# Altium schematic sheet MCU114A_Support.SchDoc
size 431 x 279 mm; Date: Not shown in title block; ApprovedBy: Not shown in title block; CheckedBy: Not shown in title block; Author: Not shown in title block; CompanyName: Not shown in title block; Engineer: Not shown in title block; Organization: Not shown in title block; Address1: Not shown in title block; Address2: Not shown in title block; Address3: Not shown in title block; Address4: Not shown in title block; DocumentNumber: 3; Revision: Use project parameter SCH_Rev; SheetNumber: 3; SheetTotal: 11; PageSetup: Record=PageOptions¦CenterHorizontal=True¦CenterVertical=True¦PrintScale=1.00¦XCorrection=1.00¦YCorrection=1.00¦PrintKind=0¦BorderSize=5000000¦LeftOffset=0¦BottomOffset=0¦Orientation=2¦PaperLength=1000¦PaperWidth=1000¦Scale=100¦PaperSource=15¦PrintQuality=600¦MediaType=1¦DitherType=10¦PaperKind=Letter¦PrintScaleMode=1
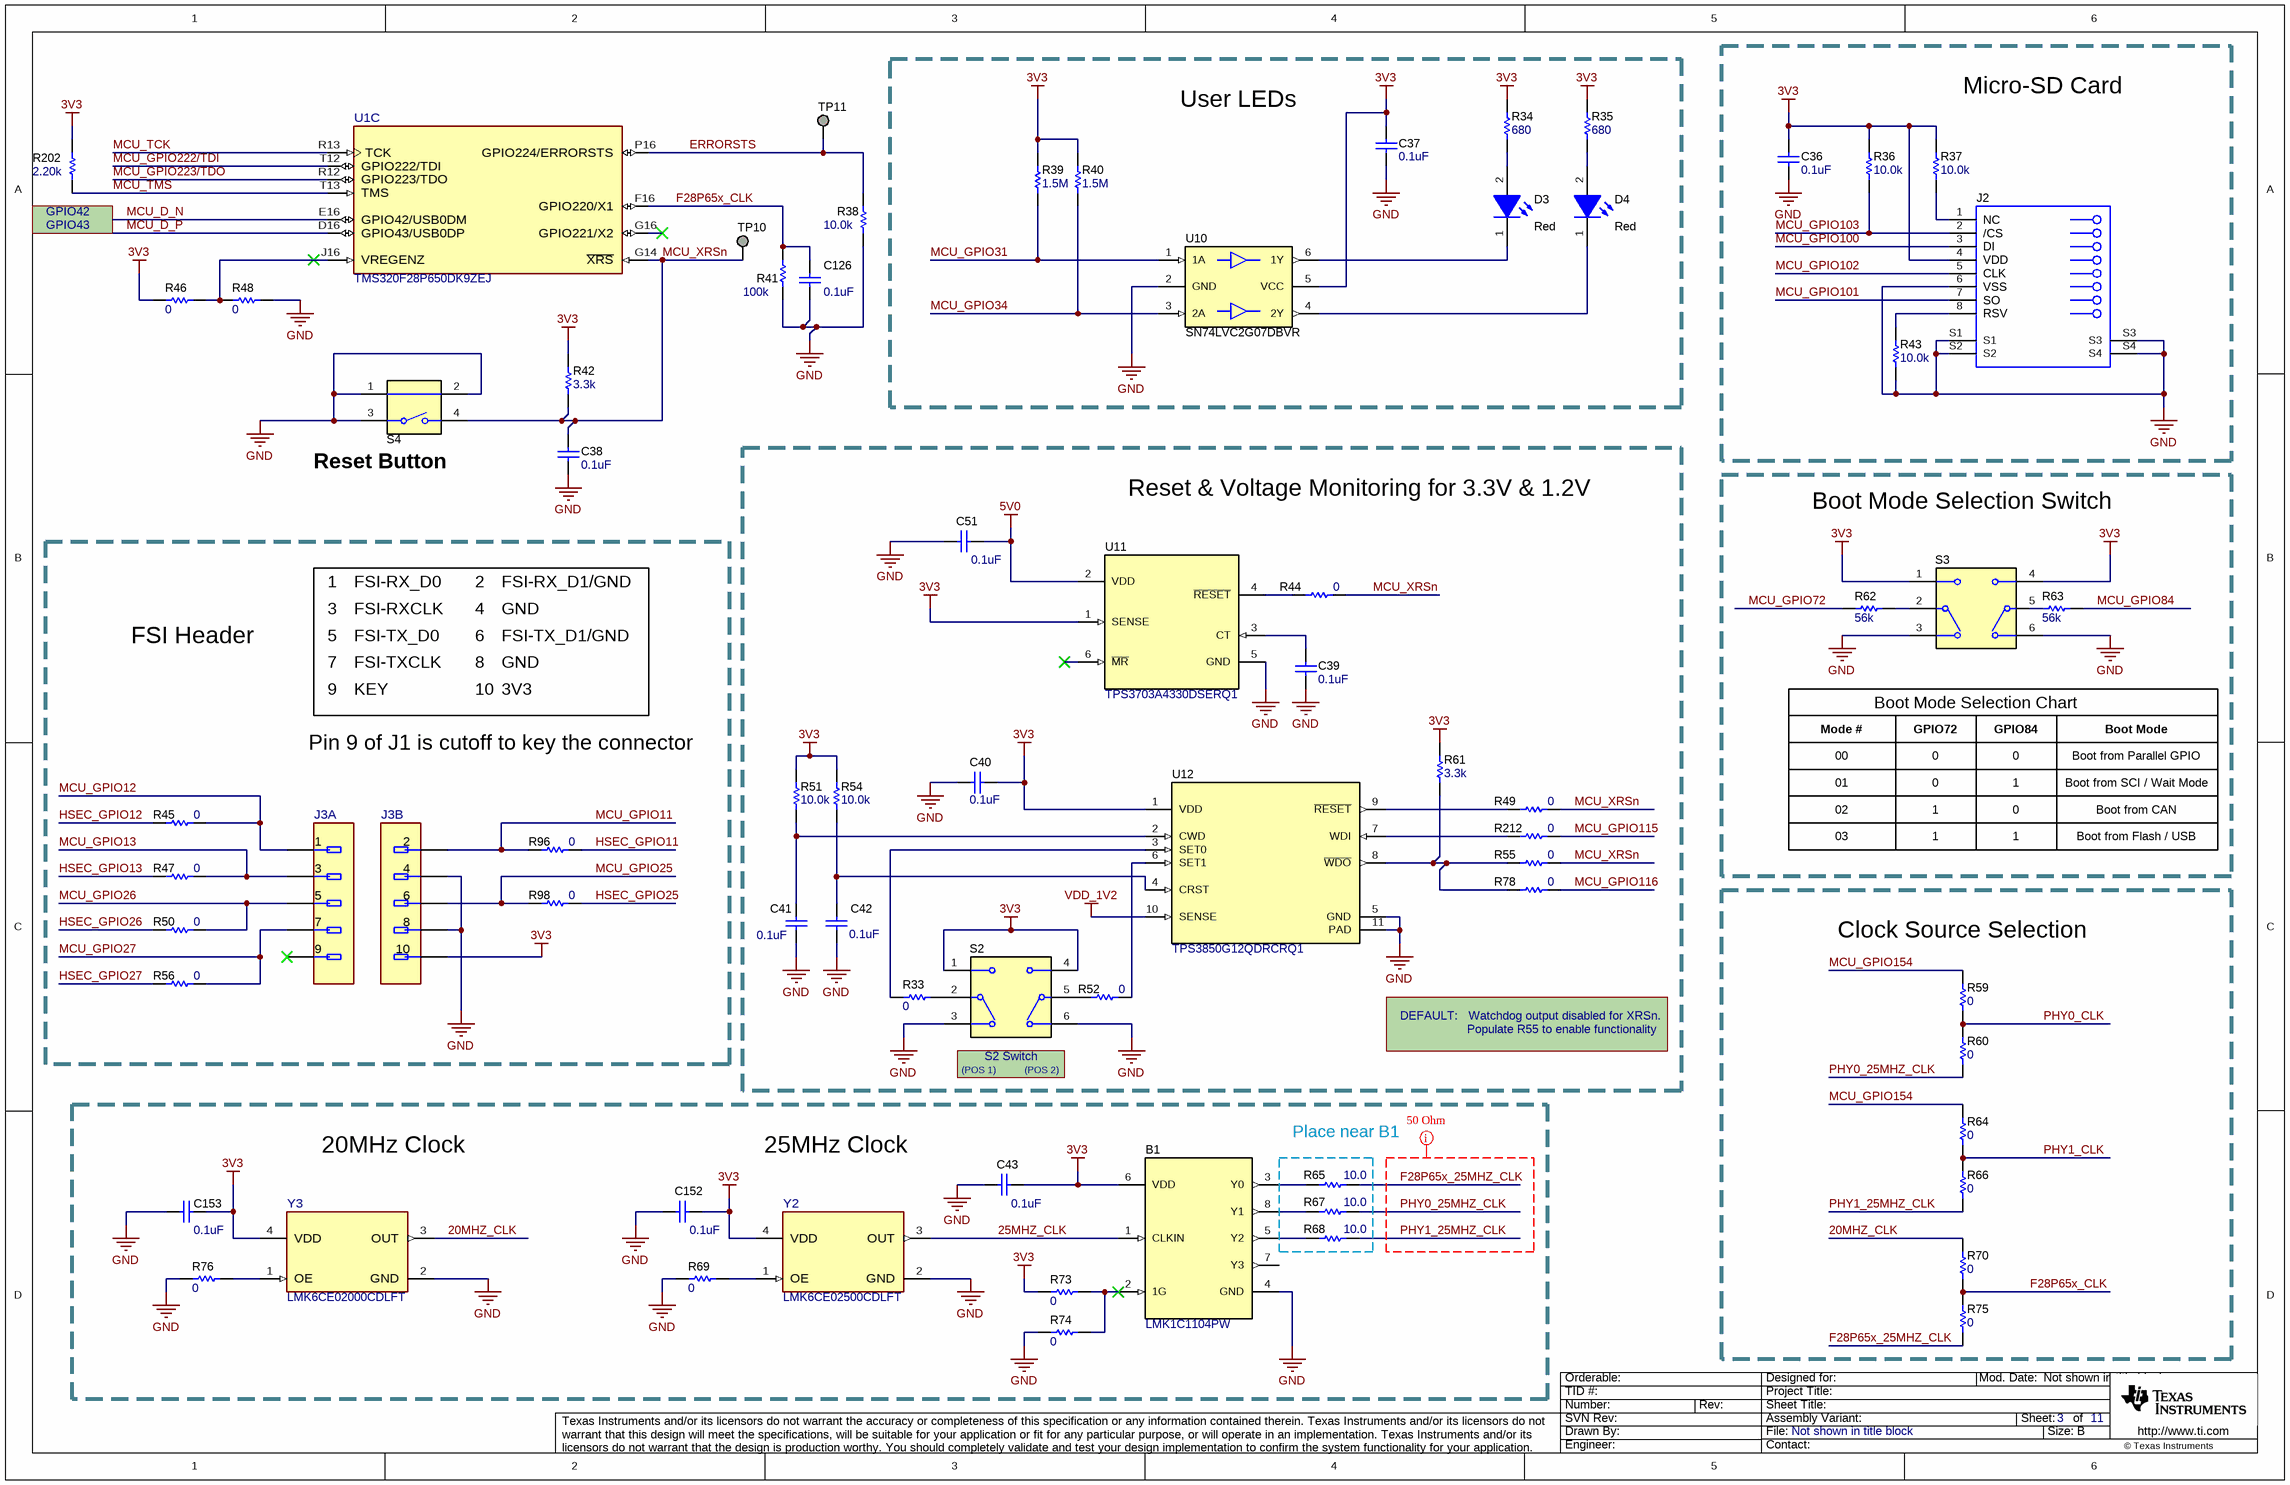
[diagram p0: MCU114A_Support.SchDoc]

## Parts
B1  LMK1C1104PW  [PW0008A_N]
C36  ValueDisplayed: 0.1uF  [0402]  (hidden comment: 885012205037)
C37  ValueDisplayed: 0.1uF  [0402]  (hidden comment: 885012205037)
C38  ValueDisplayed: 0.1uF  [0402]  (hidden comment: 885012205037)
C39  ValueDisplayed: 0.1uF  [0402]  (hidden comment: 885012205037)
C40  ValueDisplayed: 0.1uF  [0402]  (hidden comment: 885012205037)
C41  ValueDisplayed: 0.1uF  [0402]  (hidden comment: 885012205037)
C42  ValueDisplayed: 0.1uF  [0402]  (hidden comment: 885012205037)
C43  ValueDisplayed: 0.1uF  [0402]  (hidden comment: 885012205037)
C51  ValueDisplayed: 0.1uF  [0402]  (hidden comment: 885012205037)
C126  ValueDisplayed: 0.1uF  [0402]  (hidden comment: 885012205037)
C152  ValueDisplayed: 0.1uF  [0402]  (hidden comment: 885012205037)
C153  ValueDisplayed: 0.1uF  [0402]  (hidden comment: 885012205037)
D3  value Red  [WL-SMCW_RED_0805]  (hidden comment: 150080SS75000)
D4  value Red  [WL-SMCW_RED_0805]  (hidden comment: 150080SS75000)
J2  2908-05WB-MG  [3M_2908-05WB-MG]  (value not drawn)
J3  TMM-105-01-T-D  [FP-TMM-105-01-T-D_HDR10-MFG]  (value not drawn)  (parts A,B of 2)
R33  ValueDisplayed: 0  [0603]  (hidden comment: ERJ-3GEY0R00V)
R34  ValueDisplayed: 680  [0402]  (hidden comment: CRCW0402680RJNED)
R35  ValueDisplayed: 680  [0402]  (hidden comment: CRCW0402680RJNED)
R36  ValueDisplayed: 10.0k  [0402]  (hidden comment: AC0402FR-0710KL)
R37  ValueDisplayed: 10.0k  [0402]  (hidden comment: AC0402FR-0710KL)
R38  ValueDisplayed: 10.0k  [0402]  (hidden comment: AC0402FR-0710KL)
R39  ValueDisplayed: 1.5M  [0402]  (hidden comment: CRCW04021M50JNED)
R40  ValueDisplayed: 1.5M  [0402]  (hidden comment: CRCW04021M50JNED)
R41  ValueDisplayed: 100k  [0402]  (hidden comment: RG1005P-104-B-T5)
R42  ValueDisplayed: 3.3k  [0402]  (hidden comment: CRCW04023K30JNED)
R43  ValueDisplayed: 10.0k  [0402]  (hidden comment: AC0402FR-0710KL)
R44  ValueDisplayed: 0  [0603]  (hidden comment: ERJ-3GEY0R00V)
R45  ValueDisplayed: 0  [0603]  (hidden comment: ERJ-3GEY0R00V)
R46  ValueDisplayed: 0  [0402]  (hidden comment: ERJ-2GE0R00X)
R47  ValueDisplayed: 0  [0603]  (hidden comment: ERJ-3GEY0R00V)
R48  ValueDisplayed: 0  [0402]  (hidden comment: CRCW04020000Z0EDHP)
R49  ValueDisplayed: 0  [0603]  (hidden comment: ERJ-3GEY0R00V)
R50  ValueDisplayed: 0  [0603]  (hidden comment: ERJ-3GEY0R00V)
R51  ValueDisplayed: 10.0k  [0402]  (hidden comment: AC0402FR-0710KL)
R52  ValueDisplayed: 0  [0603]  (hidden comment: ERJ-3GEY0R00V)
R54  ValueDisplayed: 10.0k  [0402]  (hidden comment: AC0402FR-0710KL)
R55  ValueDisplayed: 0  [0603]  (hidden comment: ERJ-3GEY0R00V)
R56  ValueDisplayed: 0  [0603]  (hidden comment: ERJ-3GEY0R00V)
R59  ValueDisplayed: 0  [0603]  (hidden comment: ERJ-3GEY0R00V)
R60  ValueDisplayed: 0  [0603]  (hidden comment: ERJ-3GEY0R00V)
R61  ValueDisplayed: 3.3k  [0402]  (hidden comment: CRCW04023K30JNED)
R62  ValueDisplayed: 56k  [0402]  (hidden comment: CRCW040256K0JNED)
R63  ValueDisplayed: 56k  [0402]  (hidden comment: CRCW040256K0JNED)
R64  ValueDisplayed: 0  [0603]  (hidden comment: ERJ-3GEY0R00V)
R65  ValueDisplayed: 10.0  [CPF0402]  (hidden comment: CPF0402B10RE1)
R66  ValueDisplayed: 0  [0603]  (hidden comment: ERJ-3GEY0R00V)
R67  ValueDisplayed: 10.0  [CPF0402]  (hidden comment: CPF0402B10RE1)
R68  ValueDisplayed: 10.0  [CPF0402]  (hidden comment: CPF0402B10RE1)
R69  ValueDisplayed: 0  [0402]  (hidden comment: CRCW04020000Z0EDHP)
R70  ValueDisplayed: 0  [0603]  (hidden comment: ERJ-3GEY0R00V)
R73  ValueDisplayed: 0  [0402]  (hidden comment: ERJ-2GE0R00X)
R74  ValueDisplayed: 0  [0402]  (hidden comment: CRCW04020000Z0EDHP)
R75  ValueDisplayed: 0  [0603]  (hidden comment: ERJ-3GEY0R00V)
R76  ValueDisplayed: 0  [0402]  (hidden comment: CRCW04020000Z0EDHP)
R78  ValueDisplayed: 0  [0603]  (hidden comment: ERJ-3GEY0R00V)
R96  ValueDisplayed: 0  [0603]  (hidden comment: ERJ-3GEY0R00V)
R98  ValueDisplayed: 0  [0603]  (hidden comment: ERJ-3GEY0R00V)
R202  ValueDisplayed: 2.20k  [0402]  (hidden comment: CRCW04022K20FKED)
R212  ValueDisplayed: 0  [0603]  (hidden comment: ERJ-3GEY0R00V)
S2  CAS-D20TA  [SW_CAS-D20TA]  (value not drawn)
S3  CAS-D20TA  [SW_CAS-D20TA]  (value not drawn)
S4  1188E-1K2-V-TR  [SW_1188E]  (value not drawn)
TP10  TESTPOINT  [TP_50MIL-25MILHOLE]  (value not drawn)  (no BOM)
TP11  TESTPOINT  [TP_50MIL-25MILHOLE]  (value not drawn)  (no BOM)
U1  TMS320F28P650DK9ZEJ  [ZEJ0256A-MFG]  (part C of 4)
U10  SN74LVC2G07DBVR  [DBV0006A_N]
U11  TPS3703A4330DSERQ1  [DSE0006A]
U12  TPS3850G12QDRCRQ1  [DRC0010R]
Y2  LMK6CE02500CDLFT  [DLF0004A-MFG]
Y3  LMK6CE02000CDLFT  [DLF0004A-MFG]

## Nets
3V3: B1.6(VDD) C36.1 C37.1 C40.2 C43.1 C152.1 C153.1 J2.4(VDD) J3.10 R34.1 R35.1 R36.2 R37.2 R39.2 R40.2 R42.2 R46.1 R51.2 R54.2 R61.2 R73.1 R202.2 S2.1 S2.4 S3.1 S3.4 U10.5(VCC) U11.1(SENSE) U12.1(VDD) Y2.4(VDD) Y3.4(VDD)
5V0: C51.1 U11.2(VDD)
GND: B1.4(GND) C36.2 C37.2 C38.2 C39.2 C40.1 C41.1 C42.1 C43.2 C51.2 C126.1 C152.2 C153.2 J2.6(VSS) J2.S1 J2.S2 J2.S3 J2.S4 J3.4 J3.8 R38.1 R41.1 R43.1 R48.1 R69.2 R74.2 R76.2 S2.3 S2.6 S3.3 S3.6 S4.1 S4.2 S4.3 U10.2(GND) U11.5(GND) U12.5(GND) U12.11(PAD) Y2.2(GND) Y3.2(GND)
VDD_1V2: U12.10(SENSE)
20MHZ_CLK: R70.1 Y3.3(OUT)
25MHZ_CLK: B1.1(CLKIN) Y2.3(OUT)
ERRORSTS: R38.2 TP11.1 U1.P16(GPIO224/ERRORSTS)
F28P65x_25MHZ_CLK: R65.2 R75.2
F28P65x_CLK: C126.2 R41.2 R70.2 R75.1 U1.F16(GPIO220/X1)
HSEC_GPIO11: R96.1
HSEC_GPIO12: R45.2
HSEC_GPIO13: R47.2
HSEC_GPIO25: R98.1
HSEC_GPIO26: R50.2
HSEC_GPIO27: R56.2
MCU_D_N: U1.E16(GPIO42/USB0DM)
MCU_D_P: U1.D16(GPIO43/USB0DP)
MCU_GPIO11: J3.2 R96.2
MCU_GPIO12: J3.1 R45.1
MCU_GPIO13: J3.3 R47.1
MCU_GPIO25: J3.6 R98.2
MCU_GPIO26: J3.5 R50.1
MCU_GPIO27: J3.7 R56.1
MCU_GPIO31: R39.1 U10.1(1A)
MCU_GPIO34: R40.1 U10.3(2A)
MCU_GPIO72: R62.1
MCU_GPIO84: R63.1
MCU_GPIO100: J2.3(CMD)
MCU_GPIO101: J2.7(DAT0)
MCU_GPIO102: J2.5(CLK)
MCU_GPIO103: J2.2(CD/DAT3) R36.1
MCU_GPIO115: R212.1
MCU_GPIO116: R78.1
MCU_GPIO154: R59.1 R64.1
MCU_GPIO222/TDI: U1.T12(GPIO222/TDI)
MCU_GPIO223/TDO: U1.R12(GPIO223/TDO)
MCU_TCK: U1.R13(TCK)
MCU_TMS: R202.1 U1.T13(TMS)
MCU_XRSn: C38.1 R42.1 R44.1 R49.1 R55.1 S4.4 TP10.1 U1.G14(~{XRS})
PHY0_25MHZ_CLK: R60.2 R67.2
PHY0_CLK: R59.2 R60.1
PHY1_25MHZ_CLK: R66.2 R68.2
PHY1_CLK: R64.2 R66.1
NetB1_2: B1.2(1G) R73.2 R74.1
NetB1_3: B1.3(Y0) R65.1
NetB1_5: B1.5(Y2) R68.1
NetB1_8: B1.8(Y1) R67.1
NetC39_1: C39.1 U11.3(CT)
NetC41_2: C41.2 R51.1 U12.2(CWD)
NetC42_2: C42.2 R54.1 U12.4(CRST)
NetD3_1: D3.1(K) U10.6(1Y)
NetD3_2: D3.2(A) R34.2
NetD4_1: D4.1(K) U10.4(2Y)
NetD4_2: D4.2(A) R35.2
NetJ2_1: J2.1(DAT2) R37.1
NetJ2_8: J2.8(DAT1) R43.2
NetR33_1: R33.1 S2.2(C)
NetR33_2: R33.2 U12.3(SET0)
NetR44_2: R44.2 U11.4(~{RESET})
NetR46_2: R46.2 R48.2 U1.J16(VREGENZ)
NetR49_2: R49.2 U12.9(~{RESET})
NetR52_1: R52.1 U12.6(SET1)
NetR52_2: R52.2 S2.5(C)
NetR55_2: R55.2 R61.1 R78.2 U12.8(~{WDO})
NetR62_2: R62.2 S3.2(C)
NetR63_2: R63.2 S3.5(C)
NetR69_1: R69.1 Y2.1(OE)
NetR76_1: R76.1 Y3.1(OE)
NetR212_2: R212.2 U12.7(WDI)

Not connected (* = marked no-connect by the designer): B1 7(Y3); J3 9*; U1 G16(GPIO221/X2)*; U11 6(~{MR})*

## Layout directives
50 Ohm Impedance: Undefined: F28P65x_25MHZ_CLK, PHY0_25MHZ_CLK, PHY1_25MHZ_CLK

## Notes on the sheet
- User LEDs
- Micro-SD Card
- (near R202) GPIO42
- (near R202) GPIO43
- (near S4) Reset Button
- Reset & Voltage Monitoring for 3.3V & 1.2V
- Boot Mode Selection Switch
- FSI Header
- 1
- 3
- 5
- FSI-RX_D0
- FSI-RXCLK
- FSI-TX_D0
- 4
- 6
- 2
- FSI-RX_D1/GND
- FSI-TX_D1/GND
- GND
- 7
- 9
- FSI-TXCLK
- KEY
- 8
- 10
- 3V3
- Boot Mode Selection Chart
- Pin 9 of J1 is cutoff to key the connector
- Mode #
- 00
- GPIO72
- 0
- GPIO84
- Boot Mode
- Boot from Parallel GPIO
- 01
- 02
- 03
- Boot from SCI / Wait Mode
- Boot from CAN
- Boot from Flash / USB
- (near R59) Clock Source Selection
- DEFAULT:   Watchdog output disabled for XRSn.
- Populate R55 to enable functionality
- (near S2) (POS 1)
- (near S2) S2 Switch
- (near S2) (POS 2)
- 20MHz Clock
- 25MHz Clock
- Place near B1

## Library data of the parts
B1 = CMP-0860874-2: 3.3-V and 2.5-V LVCMOS High-Performance Clock Buffer Family, PW0008A (TSSOP-8); Alternate PartNumber: LMK1C1104PWR; Manufacturer: Texas Instruments; AEC Qualified: N; SizeZ_mm: 1.2; SizeY_mm: 3; SizeArea_mm2: 19.2; CompType: IC; SizeX_mm: 6.4; SizeAreaWB_mm2: 42; AEC Category: Q200
C36-C43 C51 C126 C152 C153 = CMP-0006228-2: CAP, CERM, 0.1 uF, 16 V, +/- 10%, X7R, 0402; Manufacturer: Wurth Elektronik; TaMin_C: -55°C; Polarized: N; SizeAreaWB_mm2: 3; Value1: Unknown; U/M: EA; Value: 0.1uF; TaMax_C: 125°C; SizeZ_mm: 0.6; SizeX_mm: 1; SizeY_mm: 0.5; Value2: 16V; Cap_F: 100nF; AEC Category: Q200
D3 = CMP-0002951-3: LED, Red, SMD; Manufacturer: Wurth Elektronik; Type: AlInGaP; Angle: 140; Vr_V: 5V; Ir_A: 25µA; Vf_V: 1.9V; Value1: 0.072W; Tjmax_C: 85°C; Io_A: 30mA; Power_TotalModule: 72mW
D4 = CMP-0002951-3: LED, Red, SMD; Manufacturer: Wurth Elektronik; Type: AlInGaP; Vf_V: 1.9V; Io_A: 30mA; Vr_V: 5V; Ir_A: 25µA; Tjmax_C: 85°C; Power_TotalModule: 72mW; Value1: 0.072W; Angle: 140
J2 = CMP-0075148-2: Connector, Micro SD, R/A, SMD; Manufacturer: 3M; Gender: Female; Row_Count: 1; Pitch_mm: 1.1; ContactFinish: Gold
J3 = CMP-0086568-1: Board-To-Board Connector, TMM Series, 10 Contacts, Header, 2 mm, Through Hole, 2 Rows; Manufacturer: Samtec; ContactFinish: Tin,Nickel; Voltage_V: 281V; Symbol Name: SYM-TMM-105-01-T-D; Row_Count: 2; Current_A: 3.2A
R33 R44 R45 R47 R49 R50 R52 R55 R56 R59 R60 R64 R66 R70 R75 R78 R96 R98 R212 = CMP-0025874-4: RES, 0, 5%, 0.1 W, AEC-Q200 Grade 0, 0603; Manufacturer: Panasonic; Power_W: 100mW; TempCo: 600 ppm/C; Value_Code: 0000; Value: 0; EIA_Code: E24; SizeX_mm: 1.6; SizeY_mm: 0.8; SizeZ_mm: 1; Value2: 0.1W; SizeArea_mm2: 1.28; AEC Qualified: Y; VDC_V: 50V; AEC Category: Q200; SizeAreaWB_mm2: 4.68
R34 R35 = CMP-0026962-3: RES, 680, 5%, 0.063 W, AEC-Q200 Grade 0, 0402; Manufacturer: Vishay-Dale; Value: 680; Value_Code: 680R; Power_W: 63mW; Value2: 0.063W; VDC_V: 50V; TempCo: 200 ppm/C; EIA_Code: E24; AEC Category: Q200; AEC Qualified: Y; AEC Grade: 0; SizeArea_mm2: 0.5; SizeX_mm: 1; SizeZ_mm: 0.6
R36-R38 R43 R51 R54 = CMP-0077731-1: RES, 10.0 k, 1%, 0.063 W, AEC-Q200 Grade 0, 0402; Manufacturer: Yageo America; Power_W: 63mW; TempCo: 100 ppm/C; Value_Code: 10k0; U/M: EA; Value: 10.0k; EIA_Code: E96; Res_ohm: 10k; SizeX_mm: 1.0; SizeY_mm: 0.5; SizeZ_mm: 0.6; Value2: 0.063W; AEC Qualified: Y; VDC_V: 50V; AEC Grade: 0; AEC Category: Q200
R39 R40 = CMP-0026863-2: RES, 1.5 M, 5%, 0.063 W, AEC-Q200 Grade 0, 0402; Manufacturer: Vishay-Dale; Power_W: 63mW; TempCo: 200 ppm/C; Value_Code: 1M50; Value: 1.5Meg; EIA_Code: E24; SizeX_mm: 1; SizeY_mm: 0.5; SizeZ_mm: 0.6; Value2: 0.063W; AEC Qualified: Y; VDC_V: 50V; AEC Category: Q200; AEC Grade: 0
R41 = CMP-0026815-1: RES, 100 k, 0.1%, 0.063 W, 0402; Manufacturer: Susumu Co Ltd; Power_W: 63mW; TempCo: 25 ppm/C; U/M: EA; Value: 100k; EIA_Code: E192; SizeX_mm: 1; SizeY_mm: 0.5; SizeZ_mm: 0.6; Value2: 0.063W; AEC Category: Q200
R42 R61 = CMP-0026918-5: RES, 3.3 k, 5%, 0.063 W, AEC-Q200 Grade 0, 0402; Manufacturer: Vishay-Dale; Power_W: 63mW; TempCo: 200 ppm/C; Value_Code: 3k30; Value: 3.3k; EIA_Code: E24; SizeX_mm: 1; SizeY_mm: 0.5; SizeZ_mm: 0.6; Value2: 0.063W; AEC Qualified: Y; VDC_V: 50V; AEC Category: Q200; AEC Grade: 0
R46 R73 = CMP-0026992-3: RES, 0, 5%, 0.1 W, AEC-Q200 Grade 0, 0402; Manufacturer: Panasonic; Power_W: 100mW; TempCo: 600 ppm/C; Value_Code: 0000; Value: 0; EIA_Code: E24; SizeX_mm: 1; SizeY_mm: 0.5; SizeZ_mm: 0.6; Value2: 0.1W; AEC Qualified: Y; VDC_V: 50V; AEC Category: Q200; SizeAreaWB_mm2: 3
R48 R69 R74 R76 = CMP-0081856-1: RES, 0, 0%, 0.2 W, AEC-Q200 Grade 0, 0402; Manufacturer: Vishay-Dale; SizeAreaWB_mm2: 3; SizeArea_mm2: 0.5; AEC Qualified: Y; AEC Category: Q200; Value: 0; SizeZ_mm: 0.6; Power_W: 200mW; VDC_V: 50V; Value2: 0.2W; SizeX_mm: 1
R62 R63 = CMP-0026949-3: RES, 56 k, 5%, 0.063 W, AEC-Q200 Grade 0, 0402; Manufacturer: Vishay-Dale; Value: 56k; Value_Code: 56k0; Power_W: 63mW; Value2: 0.063W; VDC_V: 50V; TempCo: 200 ppm/C; EIA_Code: E24; AEC Category: Q200; AEC Qualified: Y; AEC Grade: 0; SizeArea_mm2: 0.5; SizeX_mm: 1; SizeZ_mm: 0.6
R65 R67 R68 = CMP-0026765-1: RES, 10.0, 0.1%, 0.063 W, 0402; Manufacturer: TE Connectivity; Power_W: 63mW; TempCo: 25 ppm/C; Value_Code: 10R0; U/M: EA; Value: 10.0; EIA_Code: E192; Res_ohm: 10; SizeX_mm: 1; SizeY_mm: 0.5; SizeZ_mm: 0.35; Value2: 0.063W; AEC Qualified: N; AEC Category: Q200
R202 = CMP-0026231-2: RES, 2.20 k, 1%, 0.063 W, AEC-Q200 Grade 0, 0402; Manufacturer: Vishay-Dale; Power_W: 63mW; TempCo: 100 ppm/C; Value_Code: 2k20; Value: 2.20k; Res_ohm: 2.2k; SizeX_mm: 1; SizeY_mm: 0.5; SizeZ_mm: 0.6; Value2: 0.063W; AEC Qualified: Y; AEC Category: Q200; AEC Grade: 0
S2 S3 = CMP-0002233-1: Switch, Dual SPDT,  2 Pos, 0.1A, 6VDC, SMD; Manufacturer: Copal Electronics; CurrentRating_mA: 100A; SwitchFunction: On-On; VDC_V: 6V; PositionCount: 2
S4 = CMP-0002328-1: Switch, SPST, 0.05 A, 12 VDC, SMD; Manufacturer: Diptronics; SizeAreaWB_mm2: 53.9; SizeArea_mm2: 27.3; SizeX_mm: 7.8; SizeY_mm: 3.5; VDC_V: 12V; PositionCount: 1; CurrentRating_mA: 50A
TP10 TP11 = CMP-0078143-3: TEST POINT.  No entry in BOM.
U1 = CMP-0096042-2: Real-Time Microcontroller NFBGA256; Manufacturer: Texas Instruments; AEC Category: Q200; Core Architecture: C28x; Data Bus Width: 32bits; Number Of Ethernet Channels: 1; Number Of Cores: 2; CompType: IC; Number Of I/Os: 159; Interface: I2C,SPI,UART,CAN,USB,LIN,SCI,Ethernet,Other; Number Of Pwm Channels: 36; AEC Qualified: No; Number Of Timers/Counters: 6; Standoff Height: 0.35mm; Number Of Spi Channels: 4; SizeZ_mm: 1.4mm; Number Of Adc Channels: 40; Ram Size: 248KBytes; Frequency_Fixed: 200MHz; Memory Size: 1.28MBytes; Number Of A/D Converters: 3; Memory Type: FLASH
U10 = CMP-0051789-2: Dual Buffer/Driver with Open-Drain Output, DBV0006A, LARGE T&R; Manufacturer: Texas Instruments; 3-State Output: No; Bits(#): 2; F @ Nom Voltage(Max)(Mhz): 150; ICC @ Nom Voltage(Max)(mA): 0.01; Input Type: CMOS/TTL; Logic: True; Output Drive (IOL/IOH)(Max)(mA): 32/-32; Output Type: CMOS; Rating: Catalog; Sub-Family: Inverting Buffer/Driver; Technology Family: LVC; tpd @ Nom Voltage(Max)(ns): 8.6,4.4,3.7,2.9; VCC(Max)(V): 5.5; VCC(Min)(V): 1.65; Voltage(Nom)(V): 1.8,2.5,3.3,5; AEC Category: Q200; AEC Qualified: N; CompType: IC; Green_Lifecycle: Active; Green_REACh: Passed; SizeArea_mm2: 8.12; SizeAreaWB_mm2: 14.82; SizeX_mm: 2.8; SizeY_mm: 2.9; SizeZ_mm: 1.45
U11 = CMP-0750051-1: Overvoltage and Undervoltage Reset IC With Time Delay and Manual Reset, DSE0006A (WSON-6); Alternate Manufacturer: Texas Instruments; AEC Category: Q200; SizeY_mm: 1.5; AEC Qualified: Y; SizeAreaWB_mm2: 6.25; SizeZ_mm: 0.8; SizeArea_mm2: 2.25
U12 = CMP-0081428-2: Automotive Precision Voltage Supervisor With Programmable Window Watchdog Timer, DRC0010R (VSON-10); Alternate Manufacturer: Texas Instruments; SizeAreaWB_mm2: 16; SizeZ_mm: 1; SizeX_mm: 3; SizeArea_mm2: 9; CompType: IC; AEC Qualified: Y; AEC Category: Q200
Y2 = CMP-0096024-2: High-Performance BAW Oscillator; Manufacturer: Texas Instruments; Load Capacitance: 30pF; TJmax_C: +125°C; Frequency Stability: 25ppm; SizeZ_mm: 1mm; Max Supply Current: 50mA; Min Supply Voltage: 2.375V; Standoff Height: 0mm; Frequency_Fixed: 25MHz; Max Supply Voltage: 3.465V; TaMax_C: +105°C; AEC Qualified: No; TaMin_C: -40°C; AEC Category: Q200; CompType: IC
Y3 = CMP-0096023-2: High-Performance BAW Oscillator 20MHz 2.5V-3.3V ±5% VSON4; Manufacturer: Texas Instruments; TJmax_C: +125°C; Frequency Stability: 25ppm; SizeZ_mm: 1mm; Min Supply Voltage: 2.375V; TaMin_C: -40°C; Max Supply Voltage: 3.465V; Standoff Height: 0mm; TaMax_C: +105°C; Load Capacitance: 30pF; Max Supply Current: 50mA; AEC Qualified: No; AEC Category: Q200; CompType: IC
